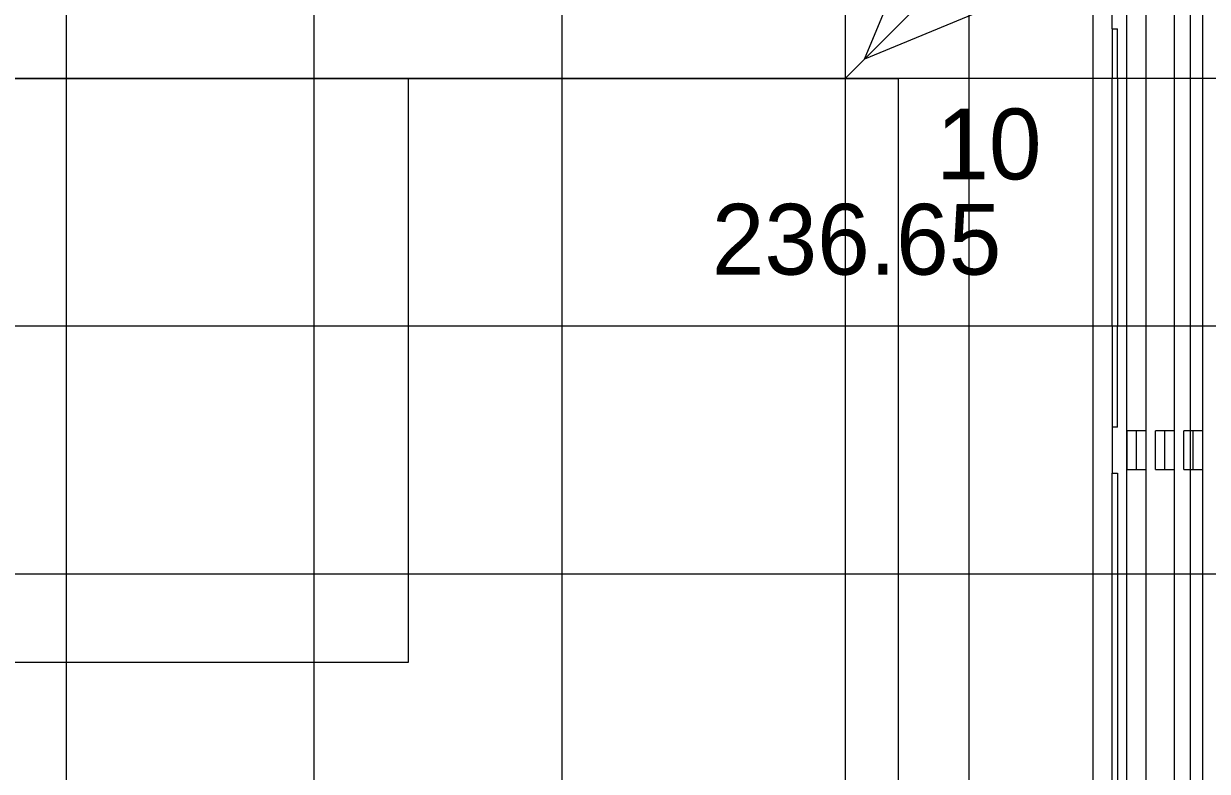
# Model space of a CAD drawing. Extents: x -264165 to -263575, y -1242333 to -1242036.
# Drawn here: x -263842.67 to -263809.23, y -1242131.46 to -1242110.33 of the extents above; entities that cross this region are included whole.
import ezdxf

# ---------------------------------------------------------------- set-up
doc = ezdxf.new("R2010")
doc.units = 0
for name, color, linetype in [('KFA_BODY_VYTYCOVAK', 7, 'Continuous'), ('KFA_HESCON_OSI_STAVBY', 7, 'Continuous'), ('KFA_SITUACIA_DRS_VYTYCOVAK_SEDA', 7, 'Continuous')]:
    doc.layers.add(name, color=color, linetype=linetype)

msp = doc.modelspace()

# ---------------------------------------------------------------- linework, layer by layer
at = {"layer": 'KFA_HESCON_OSI_STAVBY'}
for p, q in [((-263841.468, -1242080.447), (-263841.468, -1242248.737)), ((-263834.468, -1242080.447), (-263834.468, -1242248.737)), ((-263827.468, -1242080.447), (-263827.468, -1242248.737)), ((-263819.468, -1242080.447), (-263819.468, -1242248.737)), ((-263812.468, -1242080.447), (-263812.468, -1242248.737)), ((-263811.518, -1242080.447), (-263811.518, -1242248.737)), ((-263809.718, -1242080.447), (-263809.718, -1242248.737)), ((-263819.468, -1242111.882), (-263794.893, -1242087.307)), ((-263818.92, -1242111.335), (-263808.968, -1242087.307)), ((-263794.893, -1242101.382), (-263818.92, -1242111.335)), ((-263787.486, -1242111.882), (-263921.823, -1242111.882)), ((-263819.468, -1242111.882), (-263819.468, -1242111.882)), ((-263787.486, -1242118.882), (-263921.823, -1242118.882)), ((-263787.486, -1242125.882), (-263921.823, -1242125.882))]:
    msp.add_line(p, q, dxfattribs=at)
at = {"layer": 'KFA_SITUACIA_DRS_VYTYCOVAK_SEDA'}
for p, q in [((-263809.368, -1242107.378), (-263809.368, -1242111.882)), ((-263809.368, -1242107.378), (-263809.368, -1242111.882)), ((-263810.168, -1242107.709), (-263810.168, -1242111.882)), ((-263810.168, -1242107.709), (-263810.168, -1242111.882)), ((-263810.968, -1242108.041), (-263810.968, -1242111.882)), ((-263810.968, -1242108.041), (-263810.968, -1242111.882)), ((-263815.968, -1242108.382), (-263815.968, -1242220.382)), ((-263811.918, -1242110.474), (-263811.918, -1242108.434)), ((-263811.918, -1242110.474), (-263811.918, -1242108.434)), ((-263811.918, -1242110.474), (-263811.768, -1242110.474)), ((-263811.918, -1242110.474), (-263811.768, -1242110.474)), ((-263811.918, -1242110.474), (-263811.918, -1242111.882)), ((-263811.918, -1242110.474), (-263811.918, -1242111.882)), ((-263811.768, -1242111.882), (-263811.768, -1242110.474)), ((-263811.768, -1242111.882), (-263811.768, -1242110.474)), ((-263885.968, -1242111.882), (-263817.968, -1242111.882)), ((-263872.128, -1242111.882), (-263831.808, -1242111.882)), ((-263831.808, -1242111.882), (-263831.808, -1242128.382)), ((-263817.968, -1242111.882), (-263817.968, -1242216.882)), ((-263811.918, -1242118.882), (-263811.918, -1242111.882)), ((-263811.918, -1242118.882), (-263811.918, -1242111.882)), ((-263811.768, -1242111.882), (-263811.768, -1242118.882)), ((-263811.768, -1242111.882), (-263811.768, -1242118.882)), ((-263810.968, -1242111.882), (-263810.968, -1242118.882)), ((-263810.968, -1242111.882), (-263810.968, -1242118.882)), ((-263810.168, -1242111.882), (-263810.168, -1242118.882)), ((-263810.168, -1242111.882), (-263810.168, -1242118.882)), ((-263809.368, -1242111.882), (-263809.368, -1242118.882)), ((-263809.368, -1242111.882), (-263809.368, -1242118.882)), ((-263811.918, -1242118.882), (-263811.918, -1242121.732)), ((-263811.918, -1242118.882), (-263811.918, -1242121.732)), ((-263811.768, -1242121.732), (-263811.768, -1242118.882)), ((-263811.768, -1242121.732), (-263811.768, -1242118.882)), ((-263810.968, -1242118.882), (-263810.968, -1242125.882)), ((-263810.968, -1242118.882), (-263810.968, -1242125.882)), ((-263810.168, -1242118.882), (-263810.168, -1242125.882)), ((-263810.168, -1242118.882), (-263810.168, -1242125.882)), ((-263809.368, -1242118.882), (-263809.368, -1242125.882)), ((-263809.368, -1242118.882), (-263809.368, -1242125.882)), ((-263811.768, -1242121.732), (-263811.918, -1242121.732)), ((-263811.768, -1242121.732), (-263811.918, -1242121.732)), ((-263811.918, -1242121.732), (-263811.918, -1242123.032)), ((-263811.918, -1242121.732), (-263811.918, -1242123.032)), ((-263811.501, -1242122.932), (-263811.501, -1242121.832)), ((-263811.501, -1242122.932), (-263811.501, -1242121.832)), ((-263811.234, -1242121.832), (-263811.501, -1242121.832)), ((-263811.234, -1242121.832), (-263811.501, -1242121.832)), ((-263811.234, -1242122.932), (-263811.234, -1242121.832)), ((-263811.234, -1242122.932), (-263811.234, -1242121.832)), ((-263810.968, -1242121.832), (-263811.234, -1242121.832)), ((-263810.968, -1242121.832), (-263811.234, -1242121.832)), ((-263810.701, -1242122.932), (-263810.701, -1242121.832)), ((-263810.701, -1242122.932), (-263810.701, -1242121.832)), ((-263810.434, -1242121.832), (-263810.701, -1242121.832)), ((-263810.434, -1242121.832), (-263810.701, -1242121.832)), ((-263810.434, -1242122.932), (-263810.434, -1242121.832)), ((-263810.434, -1242122.932), (-263810.434, -1242121.832)), ((-263810.168, -1242121.832), (-263810.434, -1242121.832)), ((-263810.168, -1242121.832), (-263810.434, -1242121.832)), ((-263809.901, -1242122.932), (-263809.901, -1242121.832)), ((-263809.901, -1242122.932), (-263809.901, -1242121.832)), ((-263809.634, -1242121.832), (-263809.901, -1242121.832)), ((-263809.634, -1242121.832), (-263809.901, -1242121.832)), ((-263809.634, -1242122.932), (-263809.634, -1242121.832)), ((-263809.634, -1242122.932), (-263809.634, -1242121.832)), ((-263809.368, -1242121.832), (-263809.634, -1242121.832)), ((-263809.368, -1242121.832), (-263809.634, -1242121.832)), ((-263811.918, -1242123.032), (-263811.768, -1242123.032)), ((-263811.918, -1242123.032), (-263811.768, -1242123.032)), ((-263811.918, -1242125.882), (-263811.918, -1242123.032)), ((-263811.918, -1242125.882), (-263811.918, -1242123.032)), ((-263811.768, -1242123.032), (-263811.768, -1242125.882)), ((-263811.768, -1242123.032), (-263811.768, -1242125.882)), ((-263811.501, -1242122.932), (-263811.234, -1242122.932)), ((-263811.501, -1242122.932), (-263811.234, -1242122.932)), ((-263811.234, -1242122.932), (-263810.968, -1242122.932)), ((-263811.234, -1242122.932), (-263810.968, -1242122.932)), ((-263810.701, -1242122.932), (-263810.434, -1242122.932)), ((-263810.701, -1242122.932), (-263810.434, -1242122.932)), ((-263810.434, -1242122.932), (-263810.168, -1242122.932)), ((-263810.434, -1242122.932), (-263810.168, -1242122.932)), ((-263809.901, -1242122.932), (-263809.634, -1242122.932)), ((-263809.901, -1242122.932), (-263809.634, -1242122.932)), ((-263809.634, -1242122.932), (-263809.368, -1242122.932)), ((-263809.634, -1242122.932), (-263809.368, -1242122.932)), ((-263811.918, -1242132.882), (-263811.918, -1242125.882)), ((-263811.918, -1242132.882), (-263811.918, -1242125.882)), ((-263811.768, -1242125.882), (-263811.768, -1242132.882)), ((-263811.768, -1242125.882), (-263811.768, -1242132.882)), ((-263810.968, -1242125.882), (-263810.968, -1242132.882)), ((-263810.968, -1242125.882), (-263810.968, -1242132.882)), ((-263810.168, -1242125.882), (-263810.168, -1242132.882)), ((-263810.168, -1242125.882), (-263810.168, -1242132.882)), ((-263809.368, -1242125.882), (-263809.368, -1242132.882)), ((-263809.368, -1242125.882), (-263809.368, -1242132.882)), ((-263831.808, -1242128.382), (-263872.128, -1242128.382))]:
    msp.add_line(p, q, dxfattribs=at)

# ---------------------------------------------------------------- texts
at = {"layer": 'KFA_BODY_VYTYCOVAK'}
for s, p in [('10', (-263816.891, -1242114.729)), ('236.65', (-263823.231, -1242117.422))]:
    msp.add_text(s, height=2, dxfattribs=at).set_placement(p)

doc.saveas('drawing.dxf')
